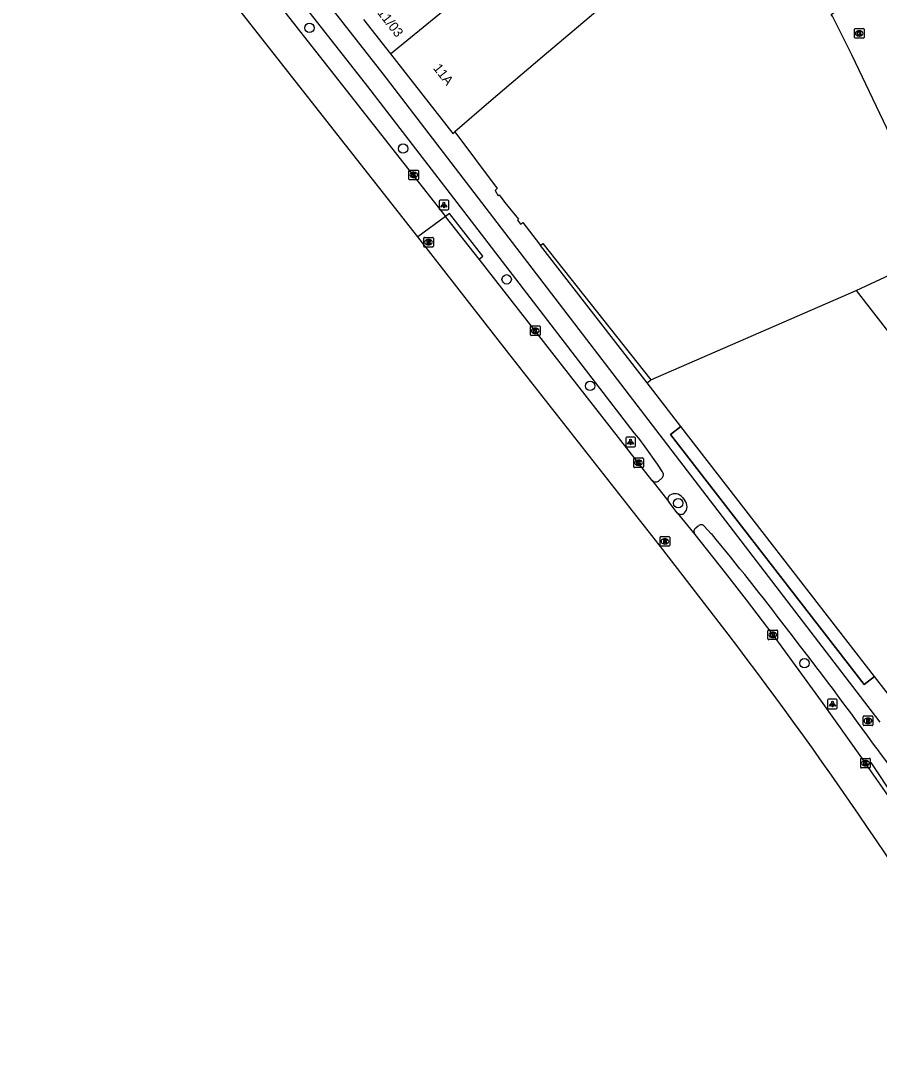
# Model space of a CAD drawing. Extents: x 161087 to 161922, y 382574 to 383873.
# Drawn here: x 161323.1 to 161412.6, y 382911.1 to 383018.9 of the extents above; entities that cross this region are included whole.
import ezdxf

# ---------------------------------------------------------------- set-up
doc = ezdxf.new("R2010")
doc.units = 0
for name, color, linetype in [('IMGEO_Boom', 7, 'Continuous'), ('IMGEO_Brandkraan', 7, 'Continuous'), ('IMGEO_Fietspad_gesloten', 7, 'Continuous'), ('IMGEO_Kolk', 7, 'Continuous'), ('IMGEO_Lichtpunt', 7, 'Continuous'), ('IMGEO_OVBaan_gesloten', 7, 'Continuous'), ('IMGEO_Pand', 7, 'Continuous'), ('IMGEO_Pand_nummerreeks', 7, 'Continuous'), ('IMGEO_Pand_overbouw', 7, 'Continuous'), ('IMGEO_Rijbaan_lokaal_open', 7, 'Continuous'), ('IMGEO_Rioolput', 7, 'Continuous'), ('IMGEO_Voetgangersgebied_open', 7, 'Continuous'), ('IMGEO_Voetpad_open', 7, 'Continuous')]:
    doc.layers.add(name, color=color, linetype=linetype)

msp = doc.modelspace()

# ---------------------------------------------------------------- linework, layer by layer
at = {"layer": 'IMGEO_Boom'}
for centre in [(161353.17, 383018.18), (161362.93, 383005.61), (161373.73, 382991.98), (161382.42, 382980.87), (161391.61, 382968.65), (161404.77, 382951.98)]:
    msp.add_circle(centre, 0.489, dxfattribs=at)
at = {"layer": 'IMGEO_Brandkraan'}
for p, q in [((161410.89, 382945.56), (161410.89, 382946.41)), ((161410.96, 382946.49), (161411.81, 382946.49)), ((161411.37, 382946.26), (161411.4, 382946.26)), ((161411.89, 382946.41), (161411.89, 382945.56)), ((161411.81, 382945.48), (161410.96, 382945.48)), ((161411.4, 382945.71), (161411.37, 382945.71))]:
    msp.add_line(p, q, dxfattribs=at)
for points in [[(161410.89, 382945.56), (161410.89, 382946.41)], [(161410.96, 382946.49), (161411.81, 382946.49)], [(161411.89, 382946.41), (161411.89, 382945.56)], [(161411.81, 382945.48), (161410.96, 382945.48)], [(161411.23, 382946.18), (161411.23, 382945.78), (161411.45, 382945.78)], [(161411.46, 382946.18), (161411.23, 382946.18)], [(161411.41, 382946.1), (161411.36, 382946.1), (161411.36, 382946.03)], [(161411.36, 382946.03), (161411.41, 382946.03)], [(161411.42, 382945.95), (161411.36, 382945.95), (161411.36, 382945.87)], [(161411.36, 382945.87), (161411.42, 382945.87)]]:
    msp.add_lwpolyline(points, dxfattribs=at)
for centre, radius, start, end in [((161410.96, 382946.41), 0.0765, 91.552, 178.448), ((161410.96, 382946.41), 0.0765, 91.552, 178.448), ((161411.81, 382946.41), 0.0765, 1.552, 88.448), ((161411.81, 382946.41), 0.0765, 1.552, 88.448), ((161410.96, 382945.56), 0.0765, 181.552, 268.448), ((161410.96, 382945.56), 0.0765, 181.552, 268.448), ((161411.41, 382946.07), 0.0379, 267.8285, 90.9355), ((161411.42, 382945.91), 0.0404, 269.8759, 90.5077), ((161411.45, 382946.04), 0.251, 268.6676, 293.5347), ((161411.47, 382946.04), 0.145, 59.4692, 91.5367), ((161411.49, 382946.09), 0.0922, 285.5137, 58.1501), ((161411.5, 382945.9), 0.105, 301.3115, 78.989), ((161411.81, 382945.56), 0.0765, 271.552, 358.448), ((161411.81, 382945.56), 0.0765, 271.552, 358.448)]:
    msp.add_arc(centre, radius, start, end, dxfattribs=at)
for centre, major_axis, ratio, start_param, end_param in [((161411.37, 382945.98), (-0.387, 0.002), 0.722429, 4.712389, 7.853982), ((161411.4, 382945.98), (-0.39, 0.002), 0.717154, 1.570796, 4.712389)]:
    msp.add_ellipse(centre, major_axis=major_axis, ratio=ratio, start_param=start_param, end_param=end_param, dxfattribs=at)
at = {"layer": 'IMGEO_Fietspad_gesloten'}
for points in [[(161323.08, 383057.94), (161323.2, 383057.89), (161324.61, 383056.16), (161359.24, 383012.06), (161368.52, 383000), (161387, 382976), (161387.47, 382975.44), (161388.13, 382974.53), (161389.41, 382972.72), (161389.95, 382971.93)], [(161412.67, 382945.83), (161395.78, 382967.85), (161371.14, 383000), (161360.86, 383013.41), (161355.3, 383020.49), (161354.66, 383021.31), (161325.56, 383058.32)], [(161389.89, 382971.26), (161389.57, 382970.96)], [(161392.06, 382969.25), (161392.3, 382968.93)], [(161393.44, 382966.1), (161393.74, 382966.32)], [(161394.33, 382966.25), (161395.06, 382965.48)], [(161412.57, 382942.73), (161415.53, 382938.76), (161418.55, 382934.54)]]:
    msp.add_lwpolyline(points, dxfattribs=at)
for centre, radius, start, end in [((161389.27, 382971.39), 0.525, 219.7231, 305.4695), ((161389.6, 382971.62), 0.463, 308.5817, 42.4392), ((161391.03, 382969.08), 0.5, 123.8715, 216.1861), ((161391.27, 382968.67), 0.974, 36.3928, 122.5741), ((161391.59, 382968.3), 0.945, 315.6491, 41.5934), ((161391.9, 382968.01), 0.521, 221.5762, 314.4791), ((161393.74, 382965.7), 0.496, 127.6771, 216.2264), ((161394.01, 382966.01), 0.402, 36.0188, 130.7877), ((161158.71, 382769.56), 307, 37.3089, 39.6565), ((160996.07, 382640.41), 514.66, 35.9748, 37.7707)]:
    msp.add_arc(centre, radius, start, end, dxfattribs=at)
at = {"layer": 'IMGEO_Kolk'}
for p, q in [((161409.98, 383017.19), (161409.98, 383018.04)), ((161410.05, 383018.11), (161410.91, 383018.11)), ((161410.47, 383017.89), (161410.49, 383017.89)), ((161410.98, 383018.04), (161410.98, 383017.19)), ((161410.91, 383017.11), (161410.05, 383017.11)), ((161410.49, 383017.33), (161410.46, 383017.33)), ((161363.61, 383003.36), (161364.47, 383003.36)), ((161363.54, 383002.43), (161363.54, 383003.28)), ((161364.47, 383002.36), (161363.61, 383002.36)), ((161364.05, 383002.58), (161364.02, 383002.58)), ((161364.03, 383003.14), (161364.05, 383003.14)), ((161364.54, 383003.28), (161364.54, 383002.43)), ((161376.21, 382986.2), (161376.21, 382987.05)), ((161376.29, 382987.13), (161377.14, 382987.13)), ((161377.14, 382986.12), (161376.29, 382986.12)), ((161376.7, 382986.9), (161376.72, 382986.9)), ((161376.72, 382986.35), (161376.7, 382986.35)), ((161377.21, 382987.05), (161377.21, 382986.2)), ((161386.98, 382972.44), (161386.98, 382973.29)), ((161387.05, 382973.37), (161387.91, 382973.37)), ((161387.98, 382973.29), (161387.98, 382972.44)), ((161387.91, 382972.37), (161387.05, 382972.37)), ((161387.49, 382972.59), (161387.46, 382972.59)), ((161387.47, 382973.15), (161387.49, 382973.15)), ((161400.96, 382954.51), (161400.96, 382955.36)), ((161401.04, 382955.44), (161401.89, 382955.44)), ((161401.45, 382955.22), (161401.48, 382955.22)), ((161401.97, 382955.36), (161401.97, 382954.51)), ((161401.89, 382954.44), (161401.04, 382954.44)), ((161401.47, 382954.66), (161401.45, 382954.66)), ((161410.63, 382941.15), (161410.63, 382942)), ((161410.7, 382942.07), (161411.55, 382942.07)), ((161411.63, 382942), (161411.63, 382941.15)), ((161411.55, 382941.07), (161410.7, 382941.07)), ((161411.11, 382941.85), (161411.14, 382941.85)), ((161411.14, 382941.29), (161411.11, 382941.29))]:
    msp.add_line(p, q, dxfattribs=at)
for points in [[(161409.98, 383017.19), (161409.98, 383018.04)], [(161410.05, 383018.11), (161410.91, 383018.11)], [(161410.3, 383017.81), (161410.42, 383017.81), (161410.42, 383017.66), (161410.55, 383017.81), (161410.72, 383017.81), (161410.57, 383017.66), (161410.72, 383017.41), (161410.57, 383017.41), (161410.49, 383017.58), (161410.42, 383017.51), (161410.42, 383017.41), (161410.3, 383017.41), (161410.3, 383017.81)], [(161410.98, 383018.04), (161410.98, 383017.19)], [(161410.91, 383017.11), (161410.05, 383017.11)], [(161363.61, 383003.36), (161364.47, 383003.36)], [(161363.54, 383002.43), (161363.54, 383003.28)], [(161364.47, 383002.36), (161363.61, 383002.36)], [(161363.86, 383003.06), (161363.98, 383003.06), (161363.98, 383002.9), (161364.11, 383003.06), (161364.28, 383003.06), (161364.13, 383002.91), (161364.28, 383002.66), (161364.13, 383002.66), (161364.05, 383002.82), (161363.98, 383002.75), (161363.98, 383002.66), (161363.86, 383002.66), (161363.86, 383003.06)], [(161364.54, 383003.28), (161364.54, 383002.43)], [(161376.21, 382986.2), (161376.21, 382987.05)], [(161376.29, 382987.13), (161377.14, 382987.13)], [(161377.14, 382986.12), (161376.29, 382986.12)], [(161376.53, 382986.82), (161376.66, 382986.82), (161376.66, 382986.67), (161376.78, 382986.82), (161376.95, 382986.82), (161376.8, 382986.67), (161376.96, 382986.42), (161376.8, 382986.42), (161376.72, 382986.59), (161376.66, 382986.52), (161376.66, 382986.42), (161376.53, 382986.42), (161376.53, 382986.82)], [(161377.21, 382987.05), (161377.21, 382986.2)], [(161386.98, 382972.44), (161386.98, 382973.29)], [(161387.05, 382973.37), (161387.91, 382973.37)], [(161387.98, 382973.29), (161387.98, 382972.44)], [(161387.91, 382972.37), (161387.05, 382972.37)], [(161387.3, 382973.07), (161387.42, 382973.07), (161387.42, 382972.92), (161387.55, 382973.07), (161387.72, 382973.07), (161387.57, 382972.92), (161387.72, 382972.67), (161387.57, 382972.67), (161387.49, 382972.83), (161387.42, 382972.77), (161387.42, 382972.67), (161387.3, 382972.67), (161387.3, 382973.07)], [(161400.96, 382954.51), (161400.96, 382955.36)], [(161401.04, 382955.44), (161401.89, 382955.44)], [(161401.28, 382955.14), (161401.41, 382955.14), (161401.41, 382954.99), (161401.54, 382955.14), (161401.7, 382955.14), (161401.56, 382954.99), (161401.71, 382954.74), (161401.56, 382954.74), (161401.47, 382954.9), (161401.41, 382954.83), (161401.41, 382954.74), (161401.28, 382954.74), (161401.28, 382955.14)], [(161401.97, 382955.36), (161401.97, 382954.51)], [(161401.89, 382954.44), (161401.04, 382954.44)], [(161410.63, 382941.15), (161410.63, 382942)], [(161410.7, 382942.07), (161411.55, 382942.07)], [(161411.63, 382942), (161411.63, 382941.15)], [(161411.55, 382941.07), (161410.7, 382941.07)], [(161410.95, 382941.77), (161411.07, 382941.77), (161411.07, 382941.62), (161411.2, 382941.77), (161411.36, 382941.77), (161411.22, 382941.62), (161411.37, 382941.37), (161411.22, 382941.37), (161411.13, 382941.54), (161411.07, 382941.47), (161411.07, 382941.37), (161410.95, 382941.37), (161410.95, 382941.77)]]:
    msp.add_lwpolyline(points, dxfattribs=at)
for centre, start, end in [((161410.06, 383018.04), 91.552, 178.448), ((161410.06, 383018.04), 91.552, 178.448), ((161410.9, 383018.04), 1.552, 88.448), ((161410.9, 383018.04), 1.552, 88.448), ((161410.06, 383017.19), 181.552, 268.448), ((161410.06, 383017.19), 181.552, 268.448), ((161410.9, 383017.19), 271.552, 358.448), ((161410.9, 383017.19), 271.552, 358.448), ((161363.62, 383003.28), 91.552, 178.448), ((161363.62, 383003.28), 91.552, 178.448), ((161364.46, 383003.28), 1.552, 88.448), ((161364.46, 383003.28), 1.552, 88.448), ((161363.62, 383002.43), 181.552, 268.448), ((161363.62, 383002.43), 181.552, 268.448), ((161364.46, 383002.43), 271.552, 358.448), ((161364.46, 383002.43), 271.552, 358.448), ((161376.29, 382987.05), 91.552, 178.448), ((161376.29, 382987.05), 91.552, 178.448), ((161376.29, 382986.2), 181.552, 268.448), ((161376.29, 382986.2), 181.552, 268.448), ((161377.14, 382987.05), 1.552, 88.448), ((161377.14, 382987.05), 1.552, 88.448), ((161377.14, 382986.2), 271.552, 358.448), ((161377.14, 382986.2), 271.552, 358.448), ((161387.05, 382973.29), 91.552, 178.448), ((161387.05, 382973.29), 91.552, 178.448), ((161387.9, 382973.29), 1.552, 88.448), ((161387.9, 382973.29), 1.552, 88.448), ((161387.05, 382972.44), 181.552, 268.448), ((161387.05, 382972.44), 181.552, 268.448), ((161387.9, 382972.44), 271.552, 358.448), ((161387.9, 382972.44), 271.552, 358.448), ((161401.04, 382955.36), 91.552, 178.448), ((161401.04, 382955.36), 91.552, 178.448), ((161401.89, 382955.36), 1.552, 88.448), ((161401.89, 382955.36), 1.552, 88.448), ((161401.04, 382954.51), 181.552, 268.448), ((161401.04, 382954.51), 181.552, 268.448), ((161401.89, 382954.51), 271.552, 358.448), ((161401.89, 382954.51), 271.552, 358.448), ((161410.7, 382942), 91.552, 178.448), ((161410.7, 382942), 91.552, 178.448), ((161411.55, 382942), 1.552, 88.448), ((161411.55, 382942), 1.552, 88.448), ((161410.7, 382941.15), 181.552, 268.448), ((161410.7, 382941.15), 181.552, 268.448), ((161411.55, 382941.15), 271.552, 358.448), ((161411.55, 382941.15), 271.552, 358.448)]:
    msp.add_arc(centre, 0.0765, start, end, dxfattribs=at)
for centre, major_axis, ratio, start_param, end_param in [((161410.47, 383017.61), (-0.387, 0.002), 0.722429, 4.712389, 7.853982), ((161410.49, 383017.61), (-0.39, 0.002), 0.717154, 1.570796, 4.712389), ((161364.03, 383002.86), (-0.387, 0.002), 0.722429, 4.712389, 7.853982), ((161364.05, 383002.86), (-0.39, 0.002), 0.717154, 1.570796, 4.712389), ((161376.7, 382986.62), (-0.387, 0.002), 0.722429, 4.712389, 7.853982), ((161376.72, 382986.62), (-0.39, 0.002), 0.717154, 1.570796, 4.712389), ((161387.47, 382972.87), (-0.387, 0.002), 0.722429, 4.712389, 7.853982), ((161387.49, 382972.87), (-0.39, 0.002), 0.717154, 1.570796, 4.712389), ((161401.45, 382954.94), (-0.387, 0.002), 0.722429, 4.712389, 7.853982), ((161401.48, 382954.94), (-0.39, 0.002), 0.717154, 1.570796, 4.712389), ((161411.11, 382941.57), (-0.387, 0.002), 0.722429, 4.712389, 7.853982), ((161411.14, 382941.57), (-0.39, 0.002), 0.717154, 1.570796, 4.712389)]:
    msp.add_ellipse(centre, major_axis=major_axis, ratio=ratio, start_param=start_param, end_param=end_param, dxfattribs=at)
at = {"layer": 'IMGEO_Lichtpunt'}
for p, q in [((161366.69, 383000.12), (161366.69, 382999.32)), ((161366.69, 383000.12), (161366.69, 382999.32)), ((161367.6, 383000.22), (161366.79, 383000.22)), ((161367.6, 383000.22), (161366.79, 383000.22)), ((161367.69, 382999.32), (161367.69, 383000.12)), ((161367.69, 382999.32), (161367.69, 383000.12)), ((161366.79, 382999.22), (161367.6, 382999.22)), ((161366.79, 382999.22), (161367.6, 382999.22)), ((161386.15, 382975.44), (161386.15, 382974.63)), ((161386.15, 382975.44), (161386.15, 382974.63)), ((161387.05, 382975.53), (161386.25, 382975.53)), ((161387.05, 382975.53), (161386.25, 382975.53)), ((161387.15, 382974.63), (161387.15, 382975.44)), ((161387.15, 382974.63), (161387.15, 382975.44)), ((161386.25, 382974.53), (161387.05, 382974.53)), ((161386.25, 382974.53), (161387.05, 382974.53)), ((161407.18, 382948.13), (161407.18, 382947.33)), ((161407.18, 382948.13), (161407.18, 382947.33)), ((161408.08, 382948.23), (161407.28, 382948.23)), ((161408.08, 382948.23), (161407.28, 382948.23)), ((161408.18, 382947.33), (161408.18, 382948.13)), ((161408.18, 382947.33), (161408.18, 382948.13)), ((161407.28, 382947.23), (161408.08, 382947.23)), ((161407.28, 382947.23), (161408.08, 382947.23))]:
    msp.add_line(p, q, dxfattribs=at)
for points in [[(161367.07, 382999.79), (161367.11, 382999.76), (161366.92, 382999.5), (161366.88, 382999.53), (161367.07, 382999.79)], [(161367.17, 382999.74), (161367.22, 382999.74), (161367.22, 382999.42), (161367.17, 382999.42), (161367.17, 382999.74)], [(161367.28, 382999.76), (161367.32, 382999.79), (161367.51, 382999.52), (161367.47, 382999.5), (161367.28, 382999.76)], [(161386.53, 382975.1), (161386.56, 382975.07), (161386.38, 382974.81), (161386.34, 382974.84), (161386.53, 382975.1)], [(161386.63, 382975.05), (161386.68, 382975.05), (161386.68, 382974.73), (161386.63, 382974.73), (161386.63, 382975.05)], [(161386.74, 382975.07), (161386.78, 382975.1), (161386.96, 382974.84), (161386.92, 382974.81), (161386.74, 382975.07)], [(161407.56, 382947.8), (161407.59, 382947.77), (161407.41, 382947.51), (161407.37, 382947.53), (161407.56, 382947.8)], [(161407.66, 382947.75), (161407.71, 382947.75), (161407.71, 382947.43), (161407.66, 382947.43), (161407.66, 382947.75)], [(161407.77, 382947.77), (161407.81, 382947.8), (161407.99, 382947.53), (161407.95, 382947.51), (161407.77, 382947.77)]]:
    msp.add_lwpolyline(points, dxfattribs=at)
for centre in [(161367.19, 382999.92), (161386.65, 382975.23), (161407.68, 382947.93)]:
    msp.add_circle(centre, 0.0994, dxfattribs=at)
for centre, start, end in [((161366.79, 383000.12), 90, 180), ((161366.79, 383000.12), 90, 180), ((161367.6, 383000.12), 0, 90), ((161367.6, 383000.12), 0, 90), ((161366.79, 382999.32), 180, 270), ((161366.79, 382999.32), 180, 270), ((161367.6, 382999.32), 270, 0), ((161367.6, 382999.32), 270, 360), ((161386.25, 382975.44), 90, 180), ((161386.25, 382975.44), 90, 180), ((161387.05, 382975.44), 0, 90), ((161387.05, 382975.44), 0, 90), ((161386.25, 382974.63), 180, 270), ((161386.25, 382974.63), 180, 270), ((161387.05, 382974.63), 270, 0), ((161387.05, 382974.63), 270, 360), ((161407.28, 382948.13), 90, 180), ((161407.28, 382948.13), 90, 180), ((161407.28, 382947.33), 180, 270), ((161407.28, 382947.33), 180, 270), ((161408.08, 382948.13), 0, 90), ((161408.08, 382948.13), 0, 90), ((161408.08, 382947.33), 270, 0), ((161408.08, 382947.33), 270, 360)]:
    msp.add_arc(centre, 0.0946, start, end, dxfattribs=at)
at = {"layer": 'IMGEO_OVBaan_gesloten'}
for points in [[(161325.44, 383051.89), (161366.21, 383000), (161367.36, 382998.52)], [(161364.47, 382996.4), (161349.39, 383015.58), (161339.71, 383027.96), (161323.37, 383048.79)], [(161367.36, 382998.52), (161364.47, 382996.4)], [(161370.85, 382994.09), (161367.36, 382998.52)], [(161396.8, 382955), (161390, 382963.84), (161373.96, 382984.24), (161364.47, 382996.4)], [(161388.86, 382971.06), (161370.85, 382994.09)], [(161388.86, 382971.06), (161390.62, 382968.78)], [(161391.51, 382967.66), (161390.62, 382968.78)], [(161391.51, 382967.66), (161393.34, 382965.41)], [(161393.34, 382965.41), (161396.51, 382961.39), (161398.69, 382958.57), (161401.46, 382954.94), (161406.5, 382948.02), (161410.71, 382942.14), (161411.12, 382941.57), (161411.27, 382941.37)]]:
    msp.add_lwpolyline(points, dxfattribs=at)
for centre, radius, start, end in [((161038.04, 382680.61), 451.67, 30.6887, 37.4099), ((161230.35, 382813.31), 221.65, 31.7647, 35.2916)]:
    msp.add_arc(centre, radius, start, end, dxfattribs=at)
at = {"layer": 'IMGEO_Pand'}
for points in [[(161378.04, 383028.82), (161384.54, 383021.19), (161377.43, 383015.13), (161372.12, 383010.6), (161368.32, 383007.36)], [(161361.62, 383015.49), (161372.6, 383024.48)], [(161358.82, 383019.07), (161361.62, 383015.49)], [(161361.62, 383015.49), (161368.11, 383007.19), (161368.32, 383007.36)], [(161388.74, 382981.5), (161410.14, 382990.82)], [(161410.14, 382990.82), (161415.57, 382983.83)], [(161388.37, 382981.18), (161388.74, 382981.5)], [(161391.88, 382976.66), (161388.37, 382981.18)], [(161412.08, 382950.59), (161391.88, 382976.66)], [(161414.6, 382947.35), (161412.08, 382950.59)]]:
    msp.add_lwpolyline(points, dxfattribs=at)
at = {"layer": 'IMGEO_Pand_overbouw'}
msp.add_lwpolyline([(161412.08, 382950.59), (161391.88, 382976.66), (161390.8, 382975.82), (161411, 382949.75)], close=True, dxfattribs=at)
at = {"layer": 'IMGEO_Rijbaan_lokaal_open'}
msp.add_lwpolyline([(161410.14, 382990.82), (161415.17, 382993.16), (161417.52, 382994.23), (161419.32, 382995.05), (161418.34, 382997.21), (161417.13, 382999.86), (161414.68, 383004.94), (161414.45, 383005.42), (161409.71, 383015.36), (161407.74, 383019.33), (161407.56, 383019.58), (161412.73, 383023.53)], dxfattribs=at)
at = {"layer": 'IMGEO_Rioolput'}
for p, q in [((161365.08, 382995.42), (161365.08, 382996.28)), ((161365.16, 382996.35), (161366.01, 382996.35)), ((161365.57, 382996.13), (161365.6, 382996.13)), ((161366.09, 382996.28), (161366.09, 382995.42)), ((161366.01, 382995.35), (161365.16, 382995.35)), ((161365.59, 382995.57), (161365.57, 382995.57)), ((161389.72, 382964.25), (161389.72, 382965.11)), ((161389.79, 382965.18), (161390.65, 382965.18)), ((161390.21, 382964.96), (161390.23, 382964.96)), ((161390.72, 382965.11), (161390.72, 382964.25)), ((161390.65, 382964.18), (161389.79, 382964.18)), ((161390.23, 382964.4), (161390.2, 382964.4))]:
    msp.add_line(p, q, dxfattribs=at)
for points in [[(161365.08, 382995.42), (161365.08, 382996.28)], [(161365.16, 382996.35), (161366.01, 382996.35)], [(161365.67, 382996.05), (161365.42, 382996.05), (161365.42, 382995.65)], [(161365.42, 382995.65), (161365.55, 382995.65), (161365.55, 382995.81), (161365.56, 382995.81)], [(161365.6, 382995.97), (161365.55, 382995.97), (161365.55, 382995.89)], [(161365.55, 382995.89), (161365.6, 382995.89)], [(161366.09, 382996.28), (161366.09, 382995.42)], [(161366.01, 382995.35), (161365.16, 382995.35)], [(161365.6, 382995.78), (161365.67, 382995.65), (161365.81, 382995.65), (161365.75, 382995.78)], [(161389.72, 382964.25), (161389.72, 382965.11)], [(161389.79, 382965.18), (161390.65, 382965.18)], [(161390.31, 382964.88), (161390.06, 382964.88), (161390.06, 382964.48)], [(161390.06, 382964.48), (161390.18, 382964.48), (161390.18, 382964.64), (161390.19, 382964.64)], [(161390.23, 382964.8), (161390.18, 382964.8), (161390.18, 382964.72)], [(161390.18, 382964.72), (161390.23, 382964.72)], [(161390.24, 382964.61), (161390.31, 382964.48), (161390.45, 382964.48), (161390.38, 382964.61)], [(161390.72, 382965.11), (161390.72, 382964.25)], [(161390.65, 382964.18), (161389.79, 382964.18)]]:
    msp.add_lwpolyline(points, dxfattribs=at)
for centre, radius, start, end in [((161365.16, 382996.28), 0.0765, 91.552, 178.448), ((161365.16, 382996.28), 0.0765, 91.552, 178.448), ((161365.55, 382995.76), 0.0533, 26.0293, 88.6989), ((161365.6, 382995.87), 0.0964, 77.0061, 93.1865), ((161365.58, 382996.08), 0.19, 274.7715, 282.9687), ((161365.62, 382995.93), 0.0378, 276.6634, 79.6772), ((161365.67, 382995.94), 0.109, 350.3612, 89.416), ((161365.67, 382995.94), 0.112, 277.5842, 350.9817), ((161365.65, 382995.72), 0.108, 29.5134, 73.7905), ((161366.01, 382996.28), 0.0765, 1.552, 88.448), ((161366.01, 382996.28), 0.0765, 1.552, 88.448), ((161365.16, 382995.43), 0.0765, 181.552, 268.448), ((161365.16, 382995.43), 0.0765, 181.552, 268.448), ((161366.01, 382995.43), 0.0765, 271.552, 358.448), ((161366.01, 382995.43), 0.0765, 271.552, 358.448), ((161389.8, 382965.1), 0.0765, 91.552, 178.448), ((161389.8, 382965.1), 0.0765, 91.552, 178.448), ((161390.19, 382964.59), 0.0533, 26.0293, 88.6989), ((161390.24, 382964.7), 0.0964, 77.0061, 93.1865), ((161390.22, 382964.91), 0.19, 274.7715, 282.9687), ((161390.25, 382964.76), 0.0378, 276.6634, 79.6772), ((161390.31, 382964.77), 0.109, 350.3612, 89.416), ((161390.31, 382964.77), 0.112, 277.5842, 350.9817), ((161390.29, 382964.55), 0.108, 29.5134, 73.7905), ((161390.64, 382965.1), 0.0765, 1.552, 88.448), ((161390.64, 382965.1), 0.0765, 1.552, 88.448), ((161389.8, 382964.26), 0.0765, 181.552, 268.448), ((161389.8, 382964.26), 0.0765, 181.552, 268.448), ((161390.64, 382964.26), 0.0765, 271.552, 358.448), ((161390.64, 382964.26), 0.0765, 271.552, 358.448)]:
    msp.add_arc(centre, radius, start, end, dxfattribs=at)
for centre, major_axis, ratio, start_param, end_param in [((161365.57, 382995.85), (-0.387, 0.002), 0.722429, 4.712389, 7.853982), ((161365.6, 382995.85), (-0.39, 0.002), 0.717154, 1.570796, 4.712389), ((161390.21, 382964.68), (-0.387, 0.002), 0.722429, 4.712389, 7.853982), ((161390.23, 382964.68), (-0.39, 0.002), 0.717154, 1.570796, 4.712389)]:
    msp.add_ellipse(centre, major_axis=major_axis, ratio=ratio, start_param=start_param, end_param=end_param, dxfattribs=at)
at = {"layer": 'IMGEO_Voetgangersgebied_open'}
msp.add_lwpolyline([(161377.24, 382995.52), (161377.49, 382995.71), (161388.74, 382981.5)], dxfattribs=at)
at = {"layer": 'IMGEO_Voetpad_open'}
for points in [[(161368.32, 383007.36), (161372.75, 383001.43), (161372.53, 383001.22), (161372.85, 383000.67), (161372.94, 383000.77), (161373.55, 383000), (161374.96, 382998.24), (161374.86, 382998.14), (161375.17, 382997.73), (161375.42, 382997.89), (161376.8, 382996.09), (161377.24, 382995.52)], [(161370.85, 382994.09), (161371.24, 382994.39), (161367.76, 382998.83), (161367.36, 382998.52)], [(161388.37, 382981.18), (161377.24, 382995.52)], [(161412.08, 382950.59), (161411, 382949.75), (161390.8, 382975.82), (161391.88, 382976.66)], [(161411.27, 382941.37), (161411.68, 382941.64), (161419.22, 382930.27), (161418.8, 382930)]]:
    msp.add_lwpolyline(points, dxfattribs=at)

# ---------------------------------------------------------------- texts
at = {"layer": 'IMGEO_Pand_nummerreeks'}
for s, rotation, p in [('11-11/03', 308.0499, (161359, 383021.27)), ('11A', 308.0525, (161366.01, 383013.97))]:
    msp.add_text(s, height=1, rotation=rotation, dxfattribs=at).set_placement(p)

doc.saveas('drawing.dxf')
